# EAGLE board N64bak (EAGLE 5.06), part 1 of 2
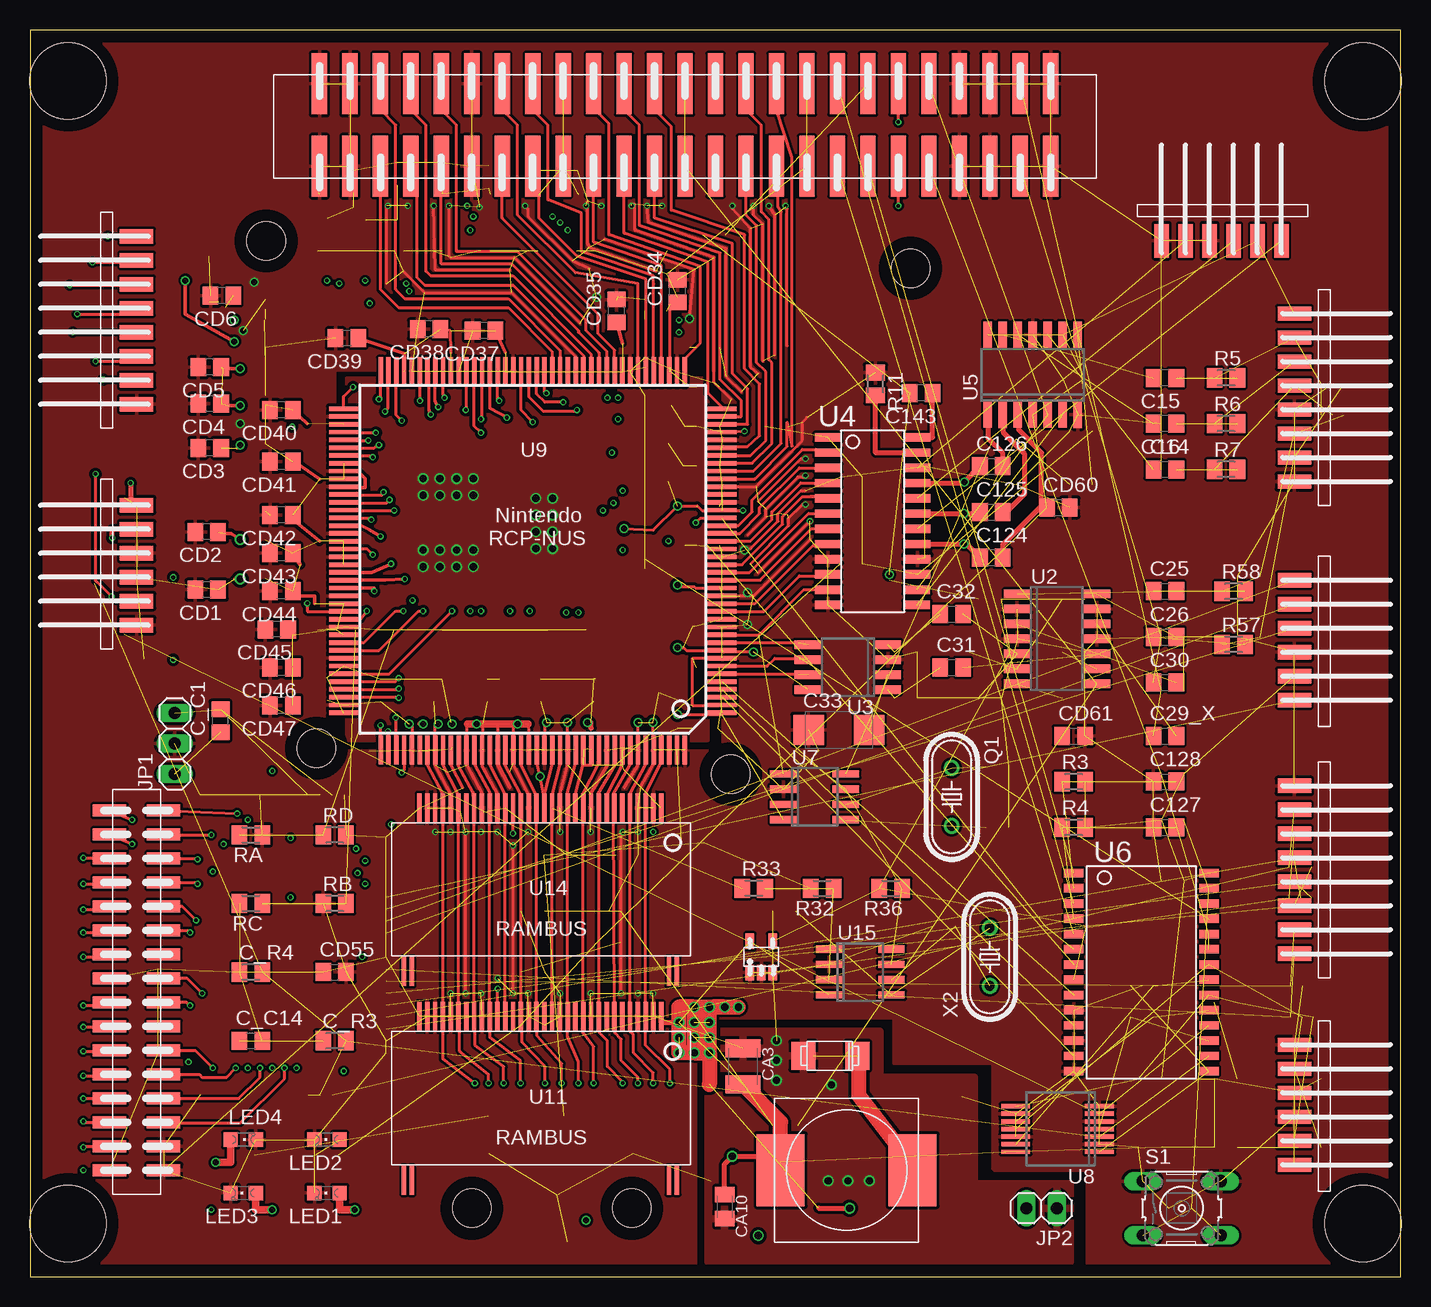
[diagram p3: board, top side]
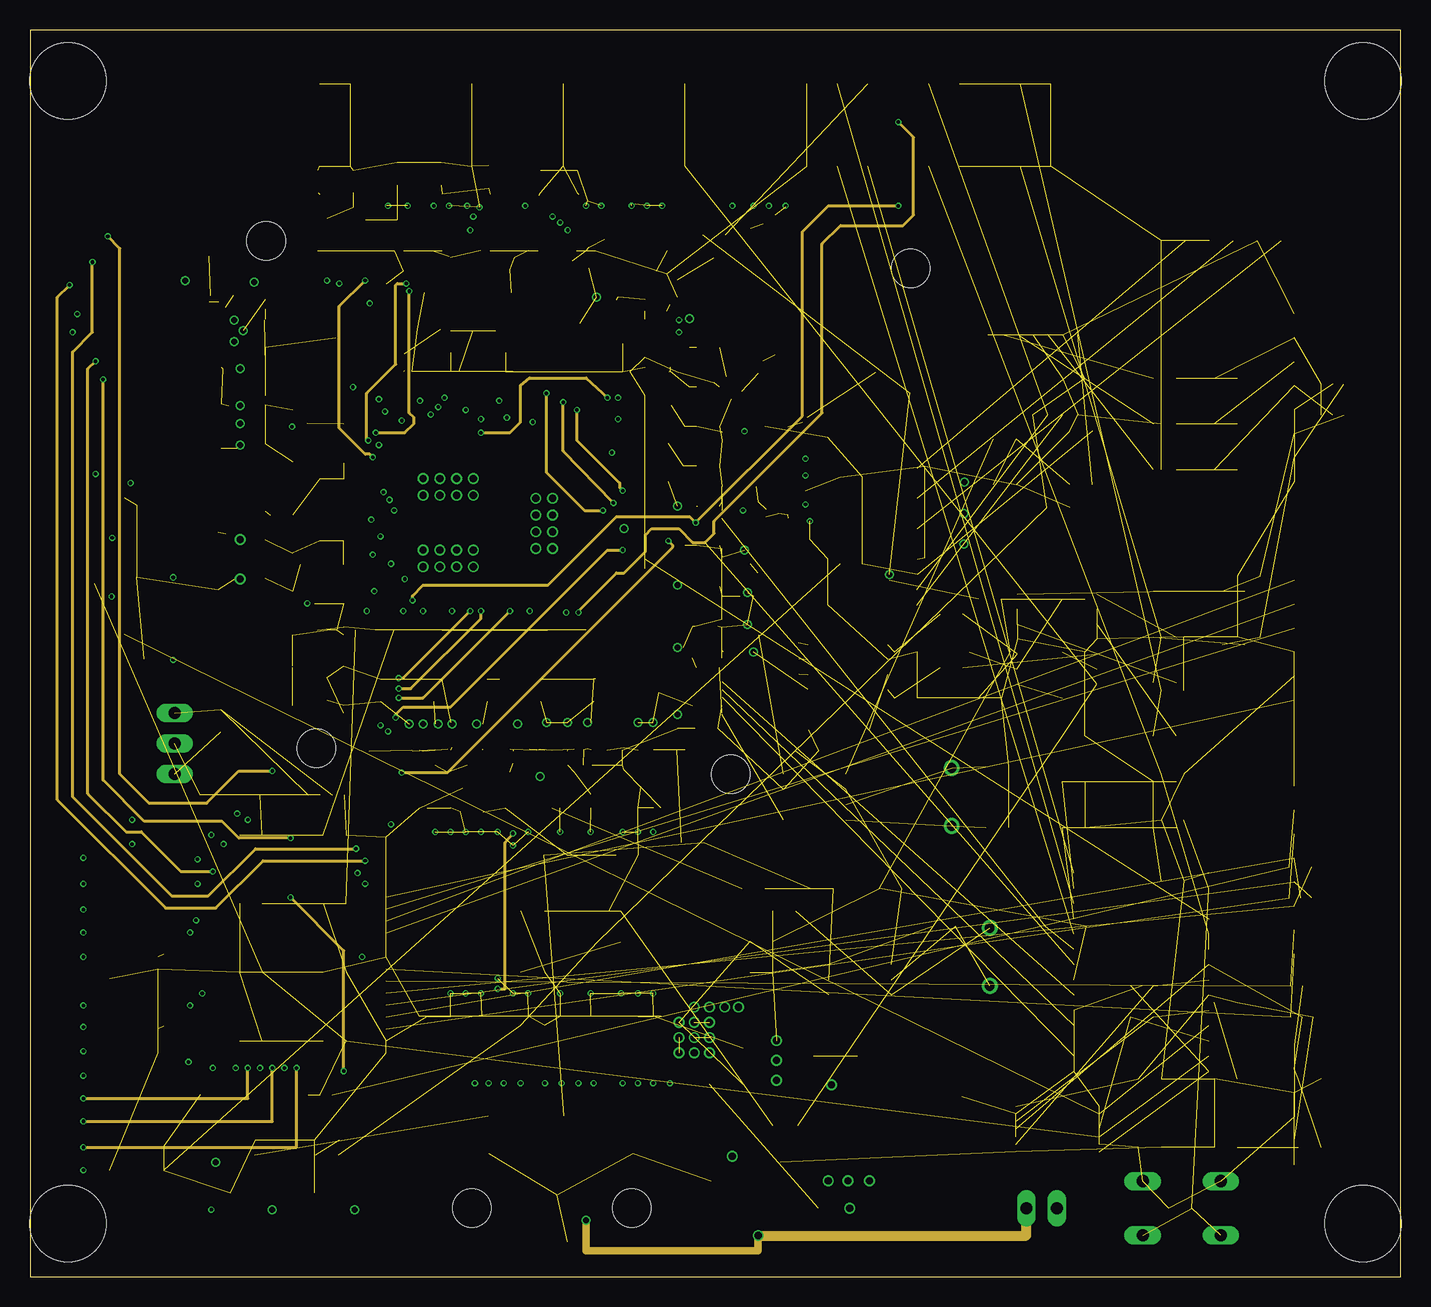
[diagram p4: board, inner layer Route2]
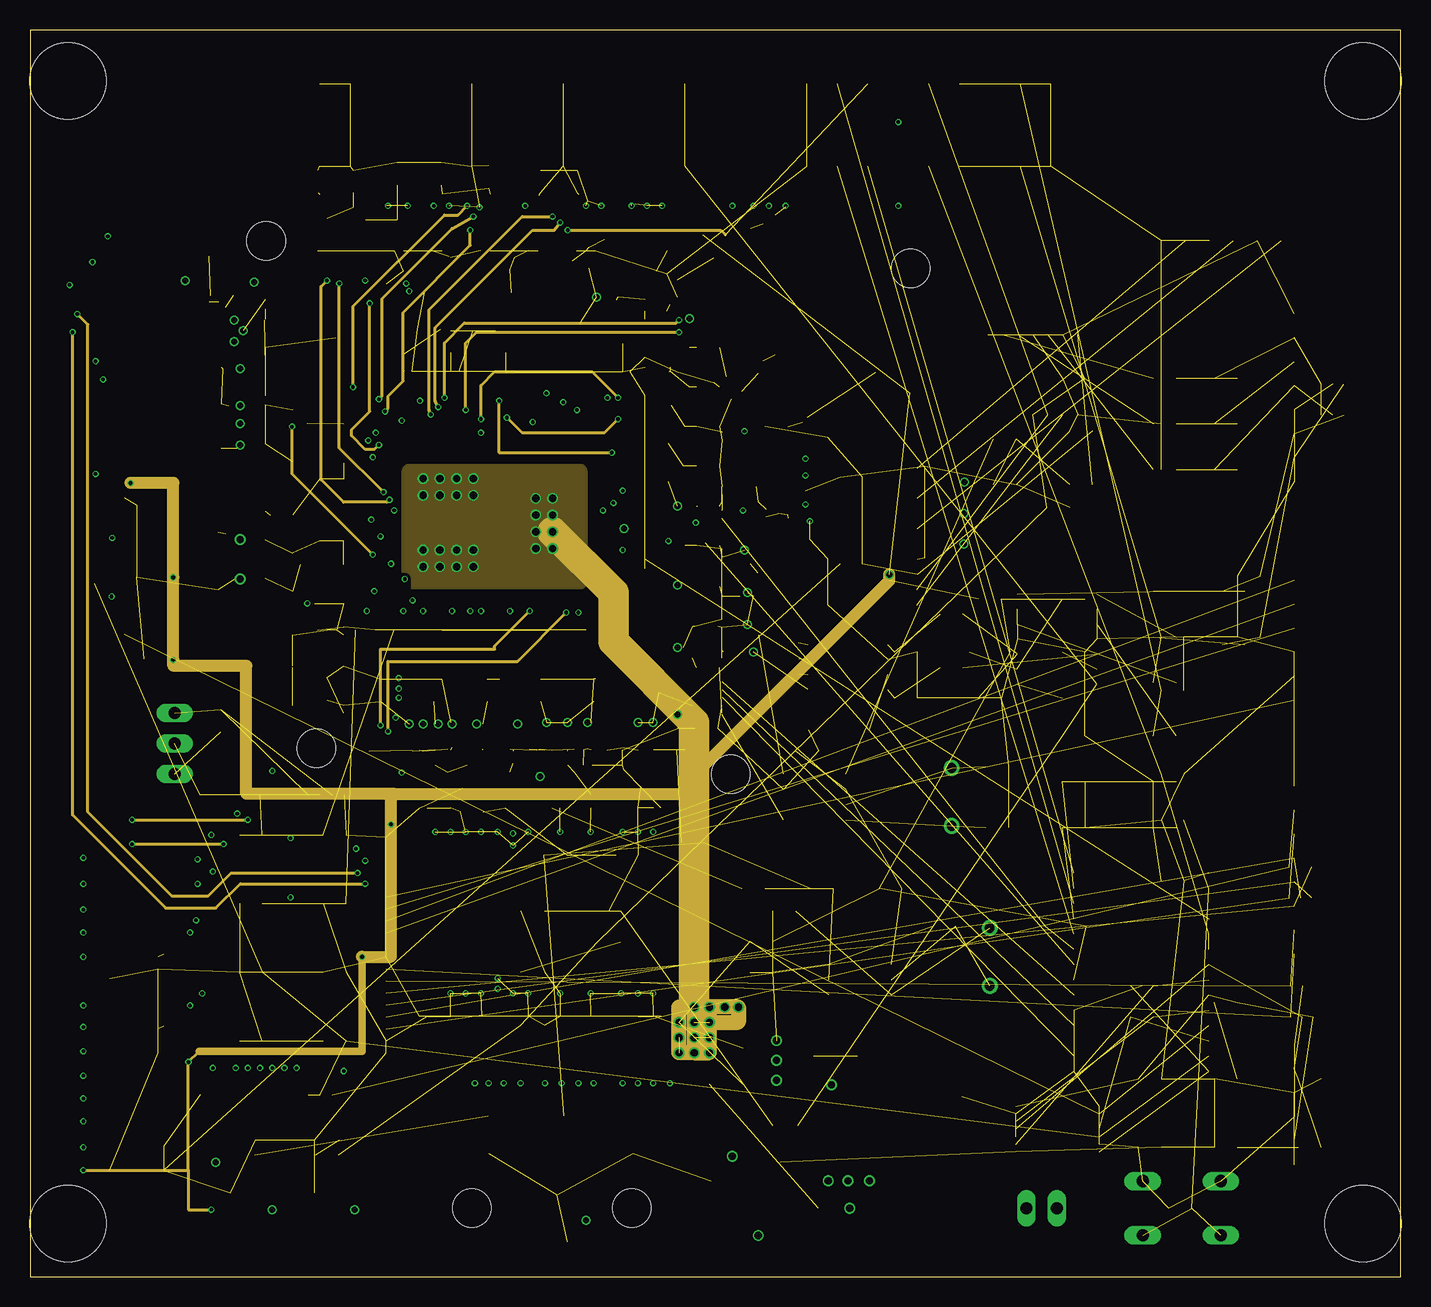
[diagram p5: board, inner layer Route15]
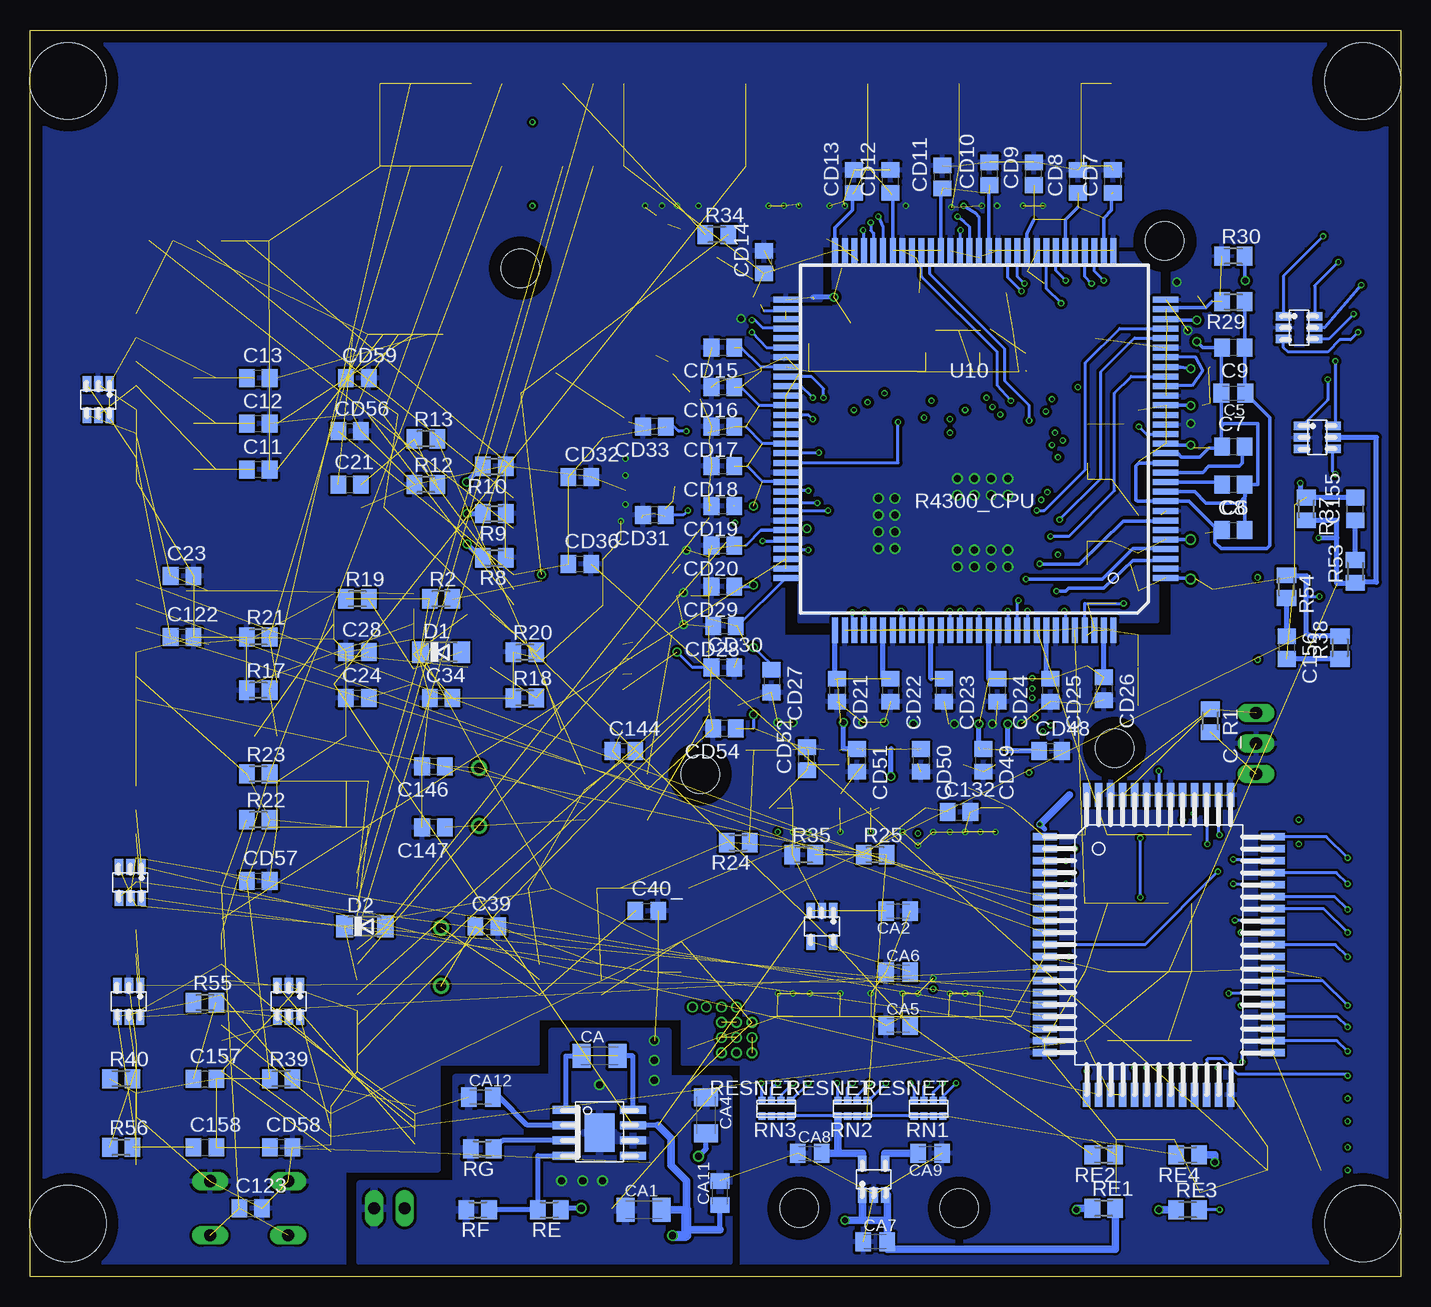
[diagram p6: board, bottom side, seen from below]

Size 114.28 x 103.94 mm. Coordinates in mm from the lower left corner, seen from the top.
Outline: 0,0 114.28,0 114.28,103.94 0,103.94 0,0
Copper layers (1*2+15*16): Top 0.035mm / dielectric 1.5mm / Route2 0.035mm / dielectric 0.15mm / Route15 0.035mm / dielectric 0.2mm / Bottom 0.035mm
Design rules "default *": minimum track width 5mil, minimum drill 10mil, track to track 6mil, track to pad 6mil, pad to pad 6mil, via to via 6mil, smd to smd 8mil, copper to edge 40mil, drill to drill 8mil, minimum pad ring 10mil, minimum via ring 4mil, stop-mask expansion 4mil, vias tented up to drill 0mil, thermal gap 10mil
Holes 3.2 mm at 19.68,86.36 23.88,44.07 58.42,41.91 36.83,5.71 50.16,5.71 73.41,84.07
Holes 6.35 mm at 3.17,99.69 111.12,99.69 3.17,4.45 111.12,4.45

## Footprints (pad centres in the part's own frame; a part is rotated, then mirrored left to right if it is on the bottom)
PSOP-8 = smd 0.65 x 2.2: 1 -1.84,-2.81; 2 -0.57,-2.81; 3 0.7,-2.81; 4 1.97,-2.81; 5 1.97,2.79; 6 0.7,2.79; 7 -0.57,2.79; 8 -1.84,2.79 | smd 3.2 x 2.5: 9 0.05,0
2MMPINHEAD-1X8 = smd 1.2 x 2.8: 1 -6,0; 2 -4,0; 3 -2,0; 4 0,0; 5 2,0; 6 4,0; 7 6,0; 8 8,0
C0805K = smd 1.3 x 1.6: 1 -1,0; 2 1,0
C0805 = smd 1.3 x 1.5: 1 -0.95,0; 2 0.95,0
C/6032-28R = smd 2.55 x 2.5: + 2.525,0; - -2.525,0
M0805 = smd 1.3 x 1.6: 1 -0.95,0; 2 0.95,0
PQFP64 = smd 0.65 x 2: 1 -9,-9.5; 2 -8,-9.5; 3 -7,-9.5; 4 -6,-9.5; 5 -5,-9.5; 6 -4,-9.5; 7 -3,-9.5; 8 -2,-9.5; 9 -1,-9.5; 10 0,-9.5; 11 1,-9.5; 12 2,-9.5; 13 3,-9.5; 14 4,-9.5; 15 5,-9.5; 16 6,-9.5; 17 7,-9.5; 18 8,-9.5; 19 9,-9.5; 33 9,9.5; 34 8,9.5; 35 7,9.5; 36 6,9.5; 37 5,9.5; 38 4,9.5; 39 3,9.5; 40 2,9.5; 41 1,9.5; 42 0,9.5; 43 -1,9.5; 44 -2,9.5; 45 -3,9.5; 46 -4,9.5; 47 -5,9.5; 48 -6,9.5; 49 -7,9.5; 50 -8,9.5; 51 -9,9.5 | smd 2 x 0.65: 20 12.5,-6; 21 12.5,-5; 22 12.5,-4; 23 12.5,-3; 24 12.5,-2; 25 12.5,-1; 26 12.5,0; 27 12.5,1; 28 12.5,2; 29 12.5,3; 30 12.5,4; 31 12.5,5; 32 12.5,6; 52 -12.5,6; 53 -12.5,5; 54 -12.5,4; 55 -12.5,3; 56 -12.5,2; 57 -12.5,1; 58 -12.5,0; 59 -12.5,-1; 60 -12.5,-2; 61 -12.5,-3; 62 -12.5,-4; 63 -12.5,-5; 64 -12.5,-6
C1206K = smd 1.5 x 2: 1 -1.5,0; 2 1.5,0
C1210K = smd 1.5 x 2.9: 1 -1.5,0; 2 1.5,0
2MMPINHEAD-1X6 = smd 1.2 x 2.8: 1 -4.73,-2.54; 2 -2.73,-2.54; 3 -0.73,-2.54; 4 1.27,-2.54; 5 3.27,-2.54; 6 5.27,-2.54
SOD80C = smd 1.4 x 1.8: A 1.7,0; C -1.7,0
STKYDIODE = smd 2.3 x 2: + 0,-2.2; - 0,2.3
1X03 = drill 1.016 long: 1 -2.54,0; 2 0,0; 3 2.54,0
1X02 = drill 1.016 long: 1 -1.27,0; 2 1.27,0
CHIPLED_0805 = smd 1.2 x 1.2: A 0,-1.05; C 0,1.05
HC49/S = drill 0.813 round: 1 -2.413,0; 2 2.413,0
RESARRAY = smd 0.6 x 0.6: 1 -1.2,-0.6; 2 -0.4,-0.6; 3 0.4,-0.6; 4 1.2,-0.6; 5 1.2,0.7; 6 0.4,0.7; 7 -0.4,0.7; 8 -1.2,0.7
B3F-10XX = drill 1.016 long: 1 -3.251,2.261; 2 3.251,2.261; 3 -3.251,-2.261; 4 3.251,-2.261
SC-74 = smd 0.7 x 1.3: 1 -0.95,-1.4; 2 0,-1.4; 3 0.95,-1.4; 4 0.95,1.2; 5 0,1.2; 6 -0.95,1.2
SO14 = smd 0.7 x 2.2: 1 -3.85,-3.295; 2 -2.6,-3.315; 3 -1.35,-3.31; 4 -0.1,-3.305; 5 1.15,-3.295; 6 2.4,-3.31; 7 3.65,-3.315; 8 3.65,3.345; 9 2.4,3.35; 10 1.15,3.35; 11 -0.1,3.35; 12 -1.35,3.35; 13 -2.6,3.35; 14 -3.85,3.35
SO8 = smd 0.7 x 2.2: 1 -1.85,-3.795; 2 -0.6,-3.815; 3 0.65,-3.81; 4 1.9,-3.805; 5 1.9,2.85; 6 0.65,2.85; 7 -0.6,2.85; 8 -1.85,2.85
SOT23-5 = smd 0.7 x 1.3: 1 -0.95,-1.3; 2 0,-1.3; 3 0.95,-1.3; 4 0.95,1.3; 5 -0.95,1.3
SO24 = smd 0.7 x 2.2: 1 -7.62,-3.707; 2 -6.35,-3.707; 3 -5.08,-3.707; 4 -3.81,-3.707; 5 -2.54,-3.707; 6 -1.27,-3.707; 7 0,-3.707; 8 1.27,-3.707; 9 2.54,-3.707; 10 3.81,-3.707; 11 5.08,-3.707; 12 6.35,-3.707; 13 6.35,3.707; 14 5.08,3.707; 15 3.81,3.739; 16 2.54,3.739; 17 1.27,3.739; 18 0,3.739; 19 -1.27,3.739; 20 -2.54,3.739; 21 -3.81,3.739; 22 -5.08,3.739; 23 -6.35,3.739; 24 -7.62,3.739
SO28W = smd 0.7 x 1.6: 1 -8.89,-5.707; 2 -7.62,-5.707; 3 -6.35,-5.707; 4 -5.08,-5.707; 5 -3.81,-5.707; 6 -2.54,-5.707; 7 -1.27,-5.707; 8 0,-5.707; 9 1.27,-5.707; 10 2.54,-5.707; 11 3.81,-5.707; 12 5.08,-5.707; 13 6.35,-5.707; 14 7.62,-5.707; 15 7.62,5.58; 16 6.35,5.58; 17 5.08,5.58; 18 3.81,5.58; 19 2.54,5.58; 20 1.27,5.58; 21 0,5.58; 22 -1.27,5.58; 23 -2.54,5.58; 24 -3.81,5.58; 25 -5.08,5.58; 26 -6.35,5.58; 27 -7.62,5.58; 28 -8.89,5.58
SO08 = smd 0.6 x 2.2: 1 -1.905,-2.6; 2 -0.635,-2.6; 3 0.635,-2.6; 4 1.905,-2.6; 5 1.905,2.6; 6 0.635,2.6; 7 -0.635,2.6; 8 -1.905,2.6
QSOP14 = smd 0.37 x 2.4: 1 -1.905,-3.56; 2 -1.27,-3.56; 3 -0.635,-3.56; 4 0,-3.56; 5 0.635,-3.56; 6 1.27,-3.56; 7 1.905,-3.56; 8 1.905,3.425; 9 1.27,3.425; 10 0.635,3.425; 11 0,3.425; 12 -0.635,3.425; 13 -1.27,3.425; 14 -1.905,3.425
PQFP160 = smd 2.4 x 0.37: 1 15.775,-12.675; 2 15.775,-12.025; 3 15.775,-11.375; 4 15.775,-10.725; 5 15.775,-10.075; 6 15.775,-9.425; 7 15.775,-8.775; 8 15.775,-8.125; 9 15.775,-7.475; 10 15.775,-6.825; 11 15.775,-6.175; 12 15.775,-5.525; 13 15.775,-4.875; 14 15.775,-4.225; 15 15.775,-3.575; 16 15.775,-2.925; 17 15.775,-2.275; 18 15.775,-1.625; 19 15.775,-0.975; 20 15.775,-0.325; 21 15.775,0.325; 22 15.775,0.975; 23 15.775,1.625; 24 15.775,2.275; 25 15.775,2.925; 26 15.775,3.575; 27 15.775,4.225; 28 15.775,4.875; 29 15.775,5.525; 30 15.775,6.175; 31 15.775,6.825; 32 15.775,7.475; 33 15.775,8.125; 34 15.775,8.775; 35 15.775,9.425; 36 15.775,10.075; 37 15.775,10.725; 38 15.775,11.375; 39 15.775,12.025; 40 15.775,12.675; 81 -15.775,12.675; 82 -15.775,12.025; 83 -15.775,11.375; 84 -15.775,10.725; 85 -15.775,10.075; 86 -15.775,9.425; 87 -15.775,8.775; 88 -15.775,8.125; 89 -15.775,7.475; 90 -15.775,6.825; 91 -15.775,6.175; 92 -15.775,5.525; 93 -15.775,4.875; 94 -15.775,4.225; 95 -15.775,3.575; 96 -15.775,2.925; 97 -15.775,2.275; 98 -15.775,1.625; 99 -15.775,0.975; 100 -15.775,0.325; 101 -15.775,-0.325; 102 -15.775,-0.975; 103 -15.775,-1.625; 104 -15.775,-2.275; 105 -15.775,-2.925; 106 -15.775,-3.575; 107 -15.775,-4.225; 108 -15.775,-4.875; 109 -15.775,-5.525; 110 -15.775,-6.175; 111 -15.775,-6.825; 112 -15.775,-7.475; 113 -15.775,-8.125; 114 -15.775,-8.775; 115 -15.775,-9.425; 116 -15.775,-10.075; 117 -15.775,-10.725; 118 -15.775,-11.375; 119 -15.775,-12.025; 120 -15.775,-12.675 | smd 0.37 x 2.4: 41 12.675,15.775; 42 12.025,15.775; 43 11.375,15.775; 44 10.725,15.775; 45 10.075,15.775; 46 9.425,15.775; 47 8.775,15.775; 48 8.125,15.775; 49 7.475,15.775; 50 6.825,15.775; 51 6.175,15.775; 52 5.525,15.775; 53 4.875,15.775; 54 4.225,15.775; 55 3.575,15.775; 56 2.925,15.775; 57 2.275,15.775; 58 1.625,15.775; 59 0.975,15.775; 60 0.325,15.775; 61 -0.325,15.775; 62 -0.975,15.775; 63 -1.625,15.775; 64 -2.275,15.775; 65 -2.925,15.775; 66 -3.575,15.775; 67 -4.225,15.775; 68 -4.875,15.775; 69 -5.525,15.775; 70 -6.175,15.775; 71 -6.825,15.775; 72 -7.475,15.775; 73 -8.125,15.775; 74 -8.775,15.775; 75 -9.425,15.775; 76 -10.075,15.775; 77 -10.725,15.775; 78 -11.375,15.775; 79 -12.025,15.775; 80 -12.675,15.775; 121 -12.675,-15.775; 122 -12.025,-15.775; 123 -11.375,-15.775; 124 -10.725,-15.775; 125 -10.075,-15.775; 126 -9.425,-15.775; 127 -8.775,-15.775; 128 -8.125,-15.775; 129 -7.475,-15.775; 130 -6.825,-15.775; 131 -6.175,-15.775; 132 -5.525,-15.775; 133 -4.875,-15.775; 134 -4.225,-15.775; 135 -3.575,-15.775; 136 -2.925,-15.775; 137 -2.275,-15.775; 138 -1.625,-15.775; 139 -0.975,-15.775; 140 -0.325,-15.775; 141 0.325,-15.775; 142 0.975,-15.775; 143 1.625,-15.775; 144 2.275,-15.775; 145 2.925,-15.775; 146 3.575,-15.775; 147 4.225,-15.775; 148 4.875,-15.775; 149 5.525,-15.775; 150 6.175,-15.775; 151 6.825,-15.775; 152 7.475,-15.775; 153 8.125,-15.775; 154 8.775,-15.775; 155 9.425,-15.775; 156 10.075,-15.775; 157 10.725,-15.775; 158 11.375,-15.775; 159 12.025,-15.775; 160 12.675,-15.775
QFP120 = smd 2.1 x 0.5: 1 15.95,-11.6; 2 15.95,-10.8; 3 15.95,-10; 4 15.95,-9.2; 5 15.95,-8.4; 6 15.95,-7.6; 7 15.95,-6.8; 8 15.95,-6; 9 15.95,-5.2; 10 15.95,-4.4; 11 15.95,-3.6; 12 15.95,-2.8; 13 15.95,-2; 14 15.95,-1.2; 15 15.95,-0.4; 16 15.95,0.4; 17 15.95,1.2; 18 15.95,2; 19 15.95,2.8; 20 15.95,3.6; 21 15.95,4.4; 22 15.95,5.2; 23 15.95,6; 24 15.95,6.8; 25 15.95,7.6; 26 15.95,8.4; 27 15.95,9.2; 28 15.95,10; 29 15.95,10.8; 30 15.95,11.6; 61 -15.7,11.6; 62 -15.7,10.8; 63 -15.7,10; 64 -15.7,9.2; 65 -15.7,8.4; 66 -15.7,7.6; 67 -15.7,6.8; 68 -15.7,6; 69 -15.7,5.2; 70 -15.7,4.4; 71 -15.7,3.6; 72 -15.7,2.8; 73 -15.7,2; 74 -15.7,1.2; 75 -15.7,0.4; 76 -15.7,-0.4; 77 -15.7,-1.2; 78 -15.7,-2; 79 -15.7,-2.8; 80 -15.7,-3.6; 81 -15.7,-4.4; 82 -15.7,-5.2; 83 -15.7,-6; 84 -15.7,-6.8; 85 -15.7,-7.6; 86 -15.7,-8.4; 87 -15.7,-9.2; 88 -15.7,-10; 89 -15.7,-10.8; 90 -15.7,-11.6 | smd 0.5 x 2.1: 31 11.6,15.7; 32 10.8,15.7; 33 10,15.7; 34 9.2,15.7; 35 8.4,15.7; 36 7.6,15.7; 37 6.8,15.7; 38 6,15.7; 39 5.2,15.7; 40 4.4,15.7; 41 3.6,15.7; 42 2.8,15.7; 43 2,15.7; 44 1.2,15.7; 45 0.4,15.7; 46 -0.4,15.7; 47 -1.2,15.7; 48 -2,15.7; 49 -2.8,15.7; 50 -3.6,15.7; 51 -4.4,15.7; 52 -5.2,15.7; 53 -6,15.7; 54 -6.8,15.7; 55 -7.6,15.7; 56 -8.4,15.7; 57 -9.2,15.7; 58 -10,15.7; 59 -10.8,15.7; 60 -11.6,15.7; 91 -11.6,-15.95; 92 -10.8,-15.95; 93 -10,-15.95; 94 -9.2,-15.95; 95 -8.4,-15.95; 96 -7.6,-15.95; 97 -6.8,-15.95; 98 -6,-15.95; 99 -5.2,-15.95; 100 -4.4,-15.95; 101 -3.6,-15.95; 102 -2.8,-15.95; 103 -2,-15.95; 104 -1.2,-15.95; 105 -0.4,-15.95; 106 0.4,-15.95; 107 1.2,-15.95; 108 2,-15.95; 109 2.8,-15.95; 110 3.6,-15.95; 111 4.4,-15.95; 112 5.2,-15.95; 113 6,-15.95; 114 6.8,-15.95; 115 7.6,-15.95; 116 8.4,-15.95; 117 9.2,-15.95; 118 10,-15.95; 119 10.8,-15.95; 120 11.6,-15.95
SHP32 = smd 0.37 x 2.4: 1 -10.075,-5.951; 2 -9.425,-5.951; 3 -8.775,-5.951; 4 -8.125,-5.951; 5 -7.475,-5.951; 6 -6.825,-5.951; 7 -6.175,-5.951; 8 -5.525,-5.951; 9 -4.875,-5.951; 10 -4.225,-5.951; 11 -3.575,-5.951; 12 -2.925,-5.951; 13 -2.275,-5.951; 14 -1.625,-5.951; 15 -0.975,-5.951; 16 -0.325,-5.951; 17 0.325,-5.951; 18 0.975,-5.951; 19 1.625,-5.951; 20 2.275,-5.951; 21 2.925,-5.951; 22 3.575,-5.951; 23 4.225,-5.951; 24 4.875,-5.951; 25 5.525,-5.951; 26 6.175,-5.951; 27 6.825,-5.951; 28 7.475,-5.951; 29 8.125,-5.951; 30 8.775,-5.951; 31 9.425,-5.951; 32 10.075,-5.951; M1 11.375,7.699; M2 10.725,7.699; M3 -10.725,7.699; M4 -11.375,7.699
PINHEAD-25X2 = smd 1.27 x 5.08: 1 -30.48,-3.302; 2 -30.48,3.556; 3 -27.94,-3.302; 4 -27.94,3.556; 5 -25.4,-3.302; 6 -25.4,3.556; 7 -22.86,-3.302; 8 -22.86,3.556; 9 -20.32,-3.302; 10 -20.32,3.556; 11 -17.78,-3.302; 12 -17.78,3.556; 13 -15.24,-3.302; 14 -15.24,3.556; 15 -12.7,-3.302; 16 -12.7,3.556; 17 -10.16,-3.302; 18 -10.16,3.556; 19 -7.62,-3.302; 20 -7.62,3.556; 21 -5.08,-3.302; 22 -5.08,3.556; 23 -2.54,-3.302; 24 -2.54,3.556; 25 0,-3.302; 26 0,3.556; 27 2.54,-3.302; 28 2.54,3.556; 29 5.08,-3.302; 30 5.08,3.556; 31 7.62,-3.302; 32 7.62,3.556; 33 10.16,-3.302; 34 10.16,3.556; 35 12.7,-3.302; 36 12.7,3.556; 37 15.24,-3.302; 38 15.24,3.556; 39 17.78,-3.302; 40 17.78,3.556; 41 20.32,-3.302; 42 20.32,3.556; 43 22.86,-3.302; 44 22.86,3.556; 45 25.4,-3.302; 46 25.4,3.556; 47 27.94,-3.302; 48 27.94,3.556; 49 30.48,-3.302; 50 30.48,3.556
2MMPINHEAD-16X2 = smd 1 x 2.8: 1 -16,-2.25; 2 -16,2.25; 3 -14,-2.25; 4 -14,2.25; 5 -12,-2.25; 6 -12,2.25; 7 -10,-2.25; 8 -10,2.25; 9 -8,-2.25; 10 -8,2.25; 11 -6,-2.25; 12 -6,2.25; 13 -4,-2.25; 14 -4,2.25; 15 -2,-2.25; 16 -2,2.25; 17 0,-2.25; 18 0,2.25; 19 2,-2.25; 20 2,2.25; 21 4,-2.25; 22 4,2.25; 23 6,-2.25; 24 6,2.25; 25 8,-2.25; 26 8,2.25; 27 10,-2.25; 28 10,2.25; 29 12,-2.25; 30 12,2.25; 31 14,-2.25; 32 14,2.25
INDUCTOR = smd 6 x 4: 1 0,5.5; 2 0,-5.5

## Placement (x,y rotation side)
3V3  LM22680  [PSOP-8]  66.8,12.06 270 bottom
AV  PINHEAD-1X8  [2MMPINHEAD-1X8]  105.41,74.3 270 top
BUTT1  PINHEAD-1X8  [2MMPINHEAD-1X8]  8.89,78.74 90 top
BUTT2  PINHEAD-1X8  [2MMPINHEAD-1X8]  105.41,34.93 270 top
C5  [C0805K]  13.97,73.66 180 bottom
C6  [C0805]  13.97,66.04 180 bottom
C7  [C0805]  13.97,69.21 0 bottom
C8  [C0805]  13.97,62.23 0 bottom
C9  [C0805]  13.97,77.47 180 bottom
C11  [C0805]  95.25,67.31 0 bottom
C12  [C0805]  95.25,71.12 0 bottom
C13  [C0805]  95.25,74.93 0 bottom
C14  [C0805]  94.62,67.31 0 top
C15  10uF  [C0805]  94.62,74.93 180 top
C16  10uF  [C0805]  94.62,71.12 180 top
C21  [C0805]  87.63,66.04 0 bottom
C23  [C0805]  101.6,58.42 0 bottom
C24  10uF  [C0805]  87,48.26 0 bottom
C25  10uF  [C0805]  94.62,57.15 0 top
C26  10uF  [C0805]  94.62,53.34 0 top
C28  10uF  [C0805]  87,52.07 0 bottom
C29_X  [C0805]  94.62,45.09 0 top
C30  [C0805]  94.62,49.53 0 top
C31  [C0805]  76.84,50.8 0 top
C32  [C0805]  76.84,55.25 0 top
C33  68uF  [C/6032-28R]  67.44,45.59 0 top
C34  10uF  [C0805]  80.01,48.26 0 bottom
C39  [C0805]  76.2,29.21 0 bottom
C40_  [C0805]  62.87,30.48 0 bottom
C122  [C0805]  101.6,53.34 0 bottom
C123  [C0805]  95.89,5.71 0 bottom
C124  c  [C0805]  80.14,59.94 0 top
C125  c  [C0805]  80.14,63.75 0 top
C126  c  [C0805]  80.14,67.56 0 top
C127  [C0805]  94.62,37.47 0 top
C128  10uF  [C0805]  94.62,41.28 0 top
C132  [C0805]  36.83,38.74 0 bottom
C143  c  [C0805]  74.29,73.66 180 top
C144  [C0805]  64.77,43.82 0 bottom
C146  [C0805]  80.65,42.55 180 bottom
C147  [C0805]  80.65,37.47 180 bottom
C155  [C0805]  3.81,64.01 90 bottom
C156  [C0805]  9.52,52.45 270 bottom
C157  [C0805]  99.69,16.51 0 bottom
C158  [C0805]  99.69,10.79 0 bottom
C_C1  [C0805]  15.88,46.36 90 top
C_C14  [C0805]  18.41,19.68 0 top
C_R1  1M0  [M0805]  15.88,46.36 270 bottom
C_R3  130R  [M0805]  25.4,19.68 0 top
C_R4  150K  [M0805]  18.41,25.4 0 top
C_U1  CNT-NUS  [PQFP64]  20.19,27.69 270 bottom
CA  [C1206K]  66.8,18.41 0 bottom
CA1  [C1206K]  63.12,5.59 0 bottom
CA2  [C0805K]  41.91,30.48 180 bottom
CA3  [C1210K]  59.44,17.53 270 top
CA4  [C1206K]  57.91,13.46 270 bottom
CA5  [C0805K]  41.91,20.95 0 bottom
CA6  470pF  [C0805K]  41.91,25.4 0 bottom
CA7  [C0805K]  43.82,2.92 0 bottom
CA8  [C0805K]  49.28,10.29 0 bottom
CA9  470pF  [C0805K]  39.24,10.29 180 bottom
CA10  [C0805K]  57.91,5.84 270 top
CA11  [C0805K]  56.77,6.98 90 bottom
CA12  [C0805K]  76.71,14.99 0 bottom
CD1  10uF  [C0805]  14.73,57.28 180 top
CD2  10uF  [C0805]  14.73,62.1 180 top
CD3  10uF  [C0805]  14.99,69.09 180 top
CD4  10uF  [C0805]  14.99,72.77 180 top
CD5  10uF  [C0805]  14.99,75.82 180 top
CD6  10uF  [C0805]  16,81.79 180 top
CD7  10uF  [C0805]  24,91.31 90 bottom
CD8  10uF  [C0805]  26.92,91.31 90 bottom
CD9  10uF  [C0805]  30.61,91.95 90 bottom
CD10  10uF  [C0805]  34.29,91.95 90 bottom
CD11  10uF  [C0805]  38.23,91.69 90 bottom
CD12  10uF  [C0805]  42.54,91.31 90 bottom
CD13  10uF  [C0805]  45.59,91.31 90 bottom
CD14  10uF  [C0805]  53.09,84.58 90 bottom
CD15  10uF  [C0805]  56.51,77.47 180 bottom
CD16  10uF  [C0805]  56.51,74.17 180 bottom
CD17  10uF  [C0805]  56.51,70.87 180 bottom
CD18  10uF  [C0805]  56.51,67.56 180 bottom
CD19  10uF  [C0805]  56.51,64.26 180 bottom
CD20  10uF  [C0805]  56.51,60.96 180 bottom
CD21  10uF  [C0805]  46.99,48.9 270 bottom
CD22  10uF  [C0805]  42.54,48.9 270 bottom
CD23  10uF  [C0805]  38.1,48.9 270 bottom
CD24  10uF  [C0805]  33.65,48.9 270 bottom
CD25  10uF  [C0805]  29.21,48.9 270 bottom
CD26  10uF  [C0805]  24.77,49.02 270 bottom
CD27  10uF  [C0805]  52.45,49.66 270 bottom
CD28  10uF  [C0805]  56.39,54.23 180 bottom
CD29  10uF  [C0805]  56.51,57.53 180 bottom
CD30  10uF  [C0805]  56.51,50.8 0 bottom
CD31  10uF  [C0805]  62.23,63.5 180 bottom
CD32  10uF  [C0805]  68.45,66.67 0 bottom
CD33  10uF  [C0805]  62.23,70.87 180 bottom
CD34  10uF  [C0805]  53.98,82.17 90 top
CD35  10uF  [C0805]  48.9,80.52 90 top
CD36  10uF  [C0805]  68.45,59.44 0 bottom
CD37  10uF  [C0805]  37.85,78.87 180 top
CD38  10uF  [C0805]  33.27,78.99 180 top
CD39  10uF  [C0805]  26.42,78.23 180 top
CD40  10uF  [C0805]  20.95,72.26 180 top
CD41  10uF  [C0805]  20.95,67.94 180 top
CD42  10uF  [C0805]  20.95,63.5 180 top
CD43  10uF  [C0805]  20.95,60.33 180 top
CD44  10uF  [C0805]  20.95,57.15 180 top
CD45  10uF  [C0805]  20.57,53.98 180 top
CD46  10uF  [C0805]  20.95,50.8 180 top
CD47  10uF  [C0805]  20.95,47.62 180 top
CD48  10uF  [C0805]  29.21,43.82 0 bottom
CD49  10uF  [C0805]  34.8,43.05 270 bottom
CD50  10uF  [C0805]  40.01,43.05 270 bottom
CD51  10uF  [C0805]  45.34,43.05 270 bottom
CD52  10uF  [C0805]  49.53,43.18 90 bottom
CD54  10uF  [C0805]  56.39,45.72 180 bottom
CD55  10uF  [C0805]  25.4,25.4 0 top
CD56  10uF  [C0805]  87.63,70.48 0 bottom
CD57  10uF  [C0805]  95.25,33.02 0 bottom
CD58  10uF  [C0805]  93.34,10.79 0 bottom
CD59  10uF  [C0805]  87,74.93 0 bottom
CD60  10uF  [C0805]  85.72,64.14 0 top
CD61  10uF  [C0805]  87,45.09 0 top
CONT1  PINHEAD-1X6  [2MMPINHEAD-1X6]  6.35,59.05 90 top
CONT2  PINHEAD-1X6  [2MMPINHEAD-1X6]  107.95,14.61 270 top
D1  PMLL4150  [SOD80C]  80.01,52.07 0 bottom
D2  PMLL4150  [SOD80C]  86.36,29.21 0 bottom
DA  STKYDIODE  [STKYDIODE]  66.68,18.41 270 top
JOY  PINHEAD-1X6  [2MMPINHEAD-1X6]  107.95,53.34 270 top
JP1  [1X03]  12.06,44.45 90 top
JP2  [1X02]  84.33,5.71 180 top
LED1  [CHIPLED_0805]  24.77,6.98 90 top
LED2  [CHIPLED_0805]  24.77,11.43 90 top
LED3  [CHIPLED_0805]  17.78,6.98 90 top
LED4  [CHIPLED_0805]  17.78,11.43 270 top
Q1  [HC49/S]  76.84,40.01 270 top
R2  2k0  [M0805]  80.01,56.52 0 bottom
R3  30K  [M0805]  87,41.28 0 top
R4  68K  [M0805]  87,37.47 0 top
R5  75R  [M0805]  99.69,74.93 0 top
R6  75R  [M0805]  99.69,71.12 0 top
R7  75R  [M0805]  99.69,67.31 0 top
R8  110R  [M0805]  75.56,59.94 180 bottom
R9  110R  [M0805]  75.56,63.63 180 bottom
R10  110R  [M0805]  75.56,67.56 180 bottom
R11  10k  [M0805]  70.48,74.42 270 top
R12  820R  [M0805]  81.28,66.04 0 bottom
R13  4k3  [M0805]  81.28,69.85 0 bottom
R17  1K  [M0805]  95.25,48.9 0 bottom
R18  10k  [M0805]  73.03,48.26 0 bottom
R19  180k  [M0805]  87,56.52 0 bottom
R20  10k  [M0805]  73.03,52.07 0 bottom
R21  1k  [M0805]  95.25,53.34 0 bottom
R22  47K  [M0805]  95.25,38.1 0 bottom
R23  10k  [M0805]  95.25,41.91 0 bottom
R24  24R  [M0805]  55.24,36.2 180 bottom
R25  130R  [M0805]  43.82,35.18 0 bottom
R29  4R7  [M0805]  13.97,81.28 180 bottom
R30  4R7  [M0805]  13.97,85.09 0 bottom
R32  150R  [M0805]  66.04,32.38 180 top
R33  33R  [M0805]  60.32,32.38 0 top
R34  47K  [M0805]  57.02,86.87 0 bottom
R35  390R  [M0805]  49.78,35.18 0 bottom
R36  51K  [M0805]  71.75,32.38 180 top
R37  750R  [M0805]  7.87,64.01 270 bottom
R38  750R  [M0805]  5.08,52.45 90 bottom
R39  750R  [M0805]  93.34,16.51 0 bottom
R40  750R  [M0805]  106.68,16.51 0 bottom
R53  130R  [M0805]  3.81,58.8 90 bottom
R54  130R  [M0805]  9.52,57.53 270 bottom
R55  130R  [M0805]  99.69,22.86 0 bottom
R56  130R  [M0805]  106.68,10.79 0 bottom
R57  1k  [M0805]  100.33,52.71 0 top
R58  1k  [M0805]  100.33,57.15 0 top
RA  OPEN  [M0805]  18.41,36.83 180 top
RB  0R  [M0805]  25.4,31.11 0 top
RC  33K  [M0805]  18.41,31.11 180 top
RD  33K  [M0805]  25.4,36.83 0 top
RE  1K4  [M0805]  70.99,5.59 180 bottom
RE1  1K4  [M0805]  24.77,5.71 0 bottom
RE2  1K4  [M0805]  24.77,10.16 180 bottom
RE3  1K4  [M0805]  17.78,5.59 0 bottom
RE4  1K4  [M0805]  17.78,10.16 180 bottom
RF  1K0  [M0805]  76.96,5.59 180 bottom
RG  191k  [M0805]  76.58,10.67 180 bottom
RGB  PINHEAD-1X6  [2MMPINHEAD-1X6]  99.06,88.9 0 top
RN1  RESNET  [RESARRAY]  39.37,14.1 180 bottom
RN2  RESNET  [RESARRAY]  45.72,14.1 180 bottom
RN3  RESNET  [RESARRAY]  52.07,14.1 180 bottom
S1  [B3F-10XX]  96.01,5.71 0 top
TVS1  TVS  [SC-74]  108.59,73.02 180 bottom
TVS2  TVS  [SC-74]  92.71,22.86 180 bottom
TVS3  TVS  [SC-74]  6.86,69.98 270 bottom
TVS4  TVS  [SC-74]  106.05,22.86 180 bottom
TVS5  TVS  [SC-74]  8.38,79.12 270 bottom
TVS6  TVS  [SC-74]  105.92,32.77 180 bottom
U2  AMP-NUS  [SO14]  85.6,53.09 270 top
U3  9480  [SO8]  67.69,50.8 90 top
U3_  U3  [SOT23-5]  60.96,26.67 0 top
U4  VDCNUS  [SO24]  70.23,62.36 270 top
U5  ENC-NUS  [SO14]  83.69,75.18 0 top
U6  PIF  [SO28W]  92.71,24.77 270 top
U7  MX8330MC  [SO08]  65.41,40.01 270 top
U8  74LS125J  [QSOP14]  85.6,12.32 90 top
U9  N64_RCP  [PQFP160]  41.91,59.69 0 top
U10  R4300_CPU  [QFP120]  35.56,69.85 0 bottom
U11  RDRAM18_NUS  [SHP32]  42.54,15.75 180 top
U12  MIC5219  [SOT23-5]  43.94,8.13 0 bottom
U13  MIC5219  [SOT23-5]  48.26,29.21 180 bottom
U14  RDRAM18_NUS  [SHP32]  42.54,33.15 180 top
U15  MX8330MC  [SO08]  69.22,25.4 270 top
U$37  PINHEAD-25X2  [PINHEAD-25X2]  54.61,95.88 0 top
U$38  PINHEAD-16X2SMALLER  [2MMPINHEAD-16X2]  8.89,22.86 270 top
U$52  INDUCTOR  [INDUCTOR]  68.07,8.89 270 top
X2  [HC49/S]  80.01,26.67 90 top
